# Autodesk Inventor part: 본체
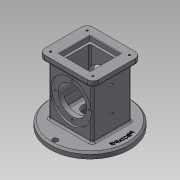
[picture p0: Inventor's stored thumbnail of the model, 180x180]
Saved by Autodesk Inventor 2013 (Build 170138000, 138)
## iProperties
Created: 2019-08
Part Number: 본체
Material: 일반
Document SubType Name: Modeling
Designer: Administrator
Density: 1 g/cm^3
Author: Administrator
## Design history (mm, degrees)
sketch "스케치1"
  geometry: C1 r 67.5 at (0, 0); 1 further point
  constraints: 1 centre point, 1 coincident
  dimensions: "d0" = 135 diameter of C1
extrude "돌출1" new body sketch "스케치1" distance "d2" = 10; taper "d3" = 0 deg
sketch "스케치2"
  geometry: L1 (37, -33)-(-37, -33); L2 (-37, -33)-(-37, 33); L3 (-37, 33)-(37, 33); L4 (37, 33)-(37, -33); L5 (37, -33)-(-37, 33); L6 (-37, -33)-(37, 33); C1 r 67.5 at (0, 0) reference
  constraints: 12 end point, 2 midpoint, 2 parallel, 1 horizontal, 1 perpendicular
  dimensions: "d4" = 66 distance of L1.end L2.end; "d6" = 74 distance of L2.end L3.end
extrude "돌출2" join sketch "스케치2" distance "d7" = 98; taper "d8" = 0 deg
sketch "스케치3"
  geometry: L1 (46, -41)-(-46, -41); L2 (-46, -41)-(-46, 41); L3 (-46, 41)-(46, 41); L4 (46, 41)-(46, -41); L5 (46, -41)-(-46, 41); L6 (-46, -41)-(46, 41); 1 further point
  constraints: 12 end point, 2 midpoint, 2 parallel, 1 horizontal, 1 perpendicular
  dimensions: "d9" = 92 distance of L2.end L3.end; "d11" = 82 distance of L3.end L1.start
extrude "돌출3" join sketch "스케치3" distance "d12" = 10; taper "d13" = 0 deg
sketch "스케치4"
  geometry: C1 r 67.5 at (0, 0) reference; C2 r 4.5 at (-59, 0); C3 r 4.5 at (0, 59); C4 r 4.5 at (0, -59); A1 r 59 centre (0, 0) between (-59, 0) and (0, 59)
  constraints: 4 centre point, 3 point on circle, 2 equal radius, 2 vertical alignment, 1 coincident, 1 horizontal alignment
  dimensions: "d14" = 118 diameter of A1; "d16" = 9 diameter of C2
extrude "돌출4" cut sketch "스케치4" stored distance "d17" = 0; taper "d18" = 0 deg
sketch "스케치7"
  geometry: L1 (-33, 98)-(-41, 98) reference; L2 (-41, 98)-(-41, 108) reference; L3 (-41, 108)-(41, 108) reference; L4 (41, 108)-(41, 98) reference; L5 (41, 98)-(33, 98) reference; L6 (33, 98)-(33, 10) reference; L7 (33, 10)-(54.5, 10) reference; L8 (54.5, 10)-(54.5, 0) reference; L9 (54.5, 0)-(-54.5, 0) reference; L10 (-54.5, 0)-(-54.5, 10) reference; L11 (-54.5, 10)-(-33, 10) reference; L12 (-33, 10)-(-33, 98) reference; L13 (-67.5, 0)-(-67.5, 10) reference; L14 (-67.5, 10)-(-63.5, 10) reference; L15 (-63.5, 10)-(-63.5, 0) reference; L16 (-63.5, 0)-(-67.5, 0) reference; L17 (67.5, 10)-(67.5, 0) reference; L18 (67.5, 0)-(63.5, 0) reference; L19 (63.5, 0)-(63.5, 10) reference; L20 (63.5, 10)-(67.5, 10) reference; L21 (-33, 54)-(33, 54); L22 (-33, 89)-(-30, 89); L23 (-30, 89)-(-30, 78); L24 (-30, 78)-(30, 78); L25 (30, 78)-(30, 89); L26 (30, 89)-(33, 89); 1 further point
  constraints: 12 end point, 3 parallel, 2 equal length, 2 midpoint, 2 perpendicular, 2 point on line
  dimensions: "d19" = 70 diameter of L22 L21; "d21" = 48 diameter of L24 L21; "d22" = 3 distance of L22.start L22.end
revolve "회전1" sketch "스케치7" stored, may be unused: angle "d23" = 90 deg
sketch "스케치8"
  geometry: L1 (22, -22)-(-22, -22); L2 (-22, -22)-(-22, 22); L3 (-22, 22)-(22, 22); L4 (22, 22)-(22, -22); L5 (22, -22)-(-22, 22); L6 (-22, -22)-(22, 22); 1 further point
  constraints: 12 end point, 2 midpoint, 2 parallel, 2 perpendicular, 1 horizontal
  dimensions: "d24" = 44 distance of L1.end L2.end
extrude "돌출5" cut sketch "스케치8" distance "d26" = 82; taper "d27" = 0 deg
sketch "스케치9"
  geometry: L1 (26, -26)-(-26, -26); L2 (-26, -26)-(-26, 26); L3 (-26, 26)-(26, 26); L4 (26, 26)-(26, -26); L5 (26, -26)-(-26, 26); L6 (-26, -26)-(26, 26); 1 further point
  constraints: 12 end point, 2 midpoint, 2 parallel, 2 perpendicular, 1 horizontal
  dimensions: "d28" = 52 distance of L1.end L2.end
extrude "돌출6" cut sketch "스케치9" distance "d30" = 8; taper "d31" = 0 deg
sketch "스케치10"
  geometry: L1 (0, 0)-(0, 18); L2 (0, 18)-(-25, 18); L3 (-54.5, 0)-(-54.5, 10) reference; L4 (-54.5, 10)-(-33, 10) reference; L5 (-33, 10)-(-33, 19) reference; L6 (-33, 19)-(-30, 19) reference; L7 (-30, 19)-(-30, 30) reference; L8 (-30, 30)-(-22, 30) reference; L9 (30, 30)-(30, 19) reference; L10 (30, 19)-(33, 19) reference; L11 (33, 19)-(33, 10) reference; L12 (33, 10)-(54.5, 10) reference; L13 (54.5, 10)-(54.5, 0) reference; L14 (54.5, 0)-(-54.5, 0) reference; L15 (41, 98)-(33, 98) reference; L16 (33, 98)-(33, 89) reference; L17 (33, 89)-(30, 89) reference; L18 (30, 89)-(30, 78) reference; L19 (30, 78)-(22, 78) reference; L20 (22, 78)-(22, 100) reference; L21 (22, 100)-(26, 100) reference; L22 (26, 100)-(26, 108) reference; L23 (26, 108)-(41, 108) reference; L24 (41, 108)-(41, 98) reference; L25 (-33, 98)-(-41, 98) reference; L26 (-41, 98)-(-41, 108) reference; L27 (-41, 108)-(-26, 108) reference; L28 (-26, 108)-(-26, 100) reference; L29 (-26, 100)-(-22, 100) reference; L30 (-22, 100)-(-22, 78) reference; L31 (-22, 78)-(-30, 78) reference; L32 (-30, 78)-(-30, 89) reference; L33 (-30, 89)-(-33, 89) reference; L34 (-33, 89)-(-33, 98) reference; L35 (-67.5, 0)-(-67.5, 10) reference; L36 (-67.5, 10)-(-63.5, 10) reference; L37 (-63.5, 10)-(-63.5, 0) reference; L38 (-63.5, 0)-(-67.5, 0) reference; L39 (67.5, 10)-(67.5, 0) reference; L40 (67.5, 0)-(63.5, 0) reference; L41 (63.5, 0)-(63.5, 10) reference; L42 (63.5, 10)-(67.5, 10) reference; L43 (-25, 18)-(-25, 0); L44 (-22, 30)-(-22, 26) reference; L45 (-22, 26)-(22, 26) reference; L46 (22, 26)-(22, 30) reference; L47 (22, 30)-(30, 30) reference
  constraints: 6 end point, 2 perpendicular, 1 point on line, 1 vertical
  dimensions: "d32" = 18 distance of L1.start L1.end; "d33" = 50 diameter of L43 L1
revolve "회전2" sketch "스케치10" stored, may be unused: angle "d34" = 90 deg
sketch "스케치11"
  geometry: L1 (-54.5, 0)-(-54.5, 10) reference; L2 (-54.5, 10)-(-33, 10) reference; L3 (-33, 10)-(-33, 19) reference; L4 (-33, 19)-(-30, 19) reference; L5 (-30, 19)-(-30, 30) reference; L6 (-30, 30)-(-22, 30) reference; L7 (-22, 30)-(-22, 26) reference; L8 (-22, 26)-(22, 26) reference; L9 (22, 26)-(22, 30) reference; L10 (22, 30)-(30, 30) reference; L11 (30, 30)-(30, 19) reference; L12 (30, 19)-(33, 19) reference; L13 (33, 19)-(33, 10) reference; L14 (33, 10)-(54.5, 10) reference; L15 (54.5, 10)-(54.5, 0) reference; L16 (54.5, 0)-(25, 0) reference; L17 (25, 0)-(25, 18) reference; L18 (25, 18)-(-25, 18) reference; L19 (-25, 18)-(-25, 0) reference; L20 (-25, 0)-(-54.5, 0) reference; L21 (41, 98)-(33, 98) reference; L22 (33, 98)-(33, 89) reference; L23 (33, 89)-(30, 89) reference; L24 (30, 89)-(30, 78) reference; L25 (30, 78)-(22, 78) reference; L26 (22, 78)-(22, 100) reference; L27 (22, 100)-(26, 100) reference; L28 (26, 100)-(26, 108) reference; L29 (26, 108)-(41, 108) reference; L30 (41, 108)-(41, 98) reference; L31 (-33, 98)-(-41, 98) reference; L32 (-41, 98)-(-41, 108) reference; L33 (-41, 108)-(-26, 108) reference; L34 (-26, 108)-(-26, 100) reference; L35 (-26, 100)-(-22, 100) reference; L36 (-22, 100)-(-22, 78) reference; L37 (-22, 78)-(-30, 78) reference; L38 (-30, 78)-(-30, 89) reference; L39 (-30, 89)-(-33, 89) reference; L40 (-33, 89)-(-33, 98) reference; L41 (-67.5, 0)-(-67.5, 10) reference; L42 (-67.5, 10)-(-63.5, 10) reference; L43 (-63.5, 10)-(-63.5, 0) reference; L44 (-63.5, 0)-(-67.5, 0) reference; L45 (67.5, 10)-(67.5, 0) reference; L46 (67.5, 0)-(63.5, 0) reference; L47 (63.5, 0)-(63.5, 10) reference; L48 (63.5, 10)-(67.5, 10) reference; L49 (0, 0)-(0, 26); L50 (0, 26)-(-12.5, 26); L51 (-12.5, 26)-(-12.5, 0); L52 (-12.5, 0)-(0, 0)
  constraints: 8 end point, 2 perpendicular, 1 midpoint, 1 point on line
  dimensions: "d35" = 25 diameter of L51 L49
revolve "회전3" sketch "스케치11" stored, may be unused: angle "d37" = 90 deg
sketch "스케치12" dims "d38" = 58
  geometry: C1 r 35 at (0, 0) reference; C2 r 24 at (0, 0) reference; 3 further points
  constraints: 2 vertical alignment, 1 coincident, 2 other
hole "구멍1" sketch "스케치12" at (0, 29) diameter "d40" = 3.242; stored, may be unused: countersink angle "d44" = 90 deg, drill point angle "d46" = 118 deg; dims "d41" = 4, "d42" = 4, "d43" = 2, "d45" = 6
sketch "스케치13"
  geometry: L1 (36, -31)-(-36, -31); L2 (-36, -31)-(-36, 31); L3 (-36, 31)-(36, 31); L4 (36, 31)-(36, -31); L5 (36, -31)-(-36, 31); L6 (-36, -31)-(36, 31); 5 further points
  constraints: 12 end point, 4 coincident, 2 midpoint, 2 parallel, 1 horizontal, 1 perpendicular
  dimensions: "d50" = 62 distance of L1.end L2.end; "d52" = 72 distance of L2.end L3.end
hole "구멍2" sketch "스케치13" at (-36, 31), (36, -31), (36, 31), (-36, -31) diameter "d53" = 3.242; stored, may be unused: countersink angle "d57" = 90 deg, drill point angle "d59" = 118 deg; dims "d54" = 4, "d55" = 4, "d56" = 2, "d58" = 6
sketch "스케치14"
  geometry: L1 (0, 89.456)-(10, 89.456) reference; L2 (10, 89.456)-(10, -23.456) reference; L3 (10, -23.456)-(0, -23.456) reference; L4 (0, -23.456)-(0, 0) reference; L5 (0, 0)-(0, 66) reference; L6 (0, 66)-(0, 89.456) reference; L7 (0, 0)-(-88, 0) reference; L8 (-88, 0)-(-88, -8) reference; L9 (-88, -8)-(-98, -8) reference; L10 (-98, -8)-(-98, 0.724) reference; L11 (-98, 74)-(-88, 74) reference; L12 (-88, 74)-(-88, 66) reference; L13 (-88, 66)-(-88, 0) reference; L14 (-88, 66)-(0, 66) reference; L15 (-98, 0.724)-(-92, 0.724) reference; L16 (-92, 3.276)-(-98, 3.276) reference; L17 (-98, 3.276)-(-98, 62.724) reference; L18 (-98, 62.724)-(-92, 62.724) reference; L19 (-92, 65.276)-(-98, 65.276) reference; L20 (-98, 65.276)-(-98, 74) reference; 4 further points
  constraints: 2 horizontal alignment, 2 vertical alignment, 1 midpoint
  dimensions: "d60" = 37 distance from line of L2 point (-27, 33); "d61" = 43 distance of point (-27, 33) point (-70, 33)
hole "구멍3" sketch "스케치14" at (-27, 33), (-70, 33) diameter "d62" = 4.917; stored, may be unused: countersink angle "d66" = 90 deg, drill point angle "d68" = 118 deg; dims "d63" = 4, "d64" = 4, "d65" = 2, "d67" = 30
fillet "모깎기2" dims "d70" = 3
fillet "모깎기3" dims "d71" = 3
fillet "모깎기4" dims "d72" = 10
fillet "모깎기5" dims "d73" = 3
fillet "모깎기6" dims "d74" = 3
chamfer "모따기1" distance "d75" = 1; stored, may be unused: second distance "d76" = 2, angle "d77" = 45 deg
fillet "모깎기7" dims "d78" = 3
fillet "모깎기8" dims "d79" = 3
node "작업 평면1"
sketch "스케치15"
  geometry: C1 r 59 at (0, 0); C2 r 67.5 at (0, 0) reference; 1 further point
  constraints: 1 centre point, 1 coincident, 1 other
  dimensions: "d88" = 118 diameter of C1
feature "엠보싱1" sketch "스케치15" dims "d2" = 10, "d82" = 0.5, "d83" = 0
fillet "모깎기9" dims "d84" = 3
chamfer "모따기2" distance "d85" = 3; stored, may be unused: second distance "d86" = 2, angle "d87" = 45 deg
node "솔리드1"
pattern_circular "원형 패턴1" dims angle "d48" = 360 deg
mirror "대칭1"
node "절단 모서리 투영2"
node "절단 모서리 투영3"
node "절단 모서리 투영4"
node "절단 모서리 투영5"
